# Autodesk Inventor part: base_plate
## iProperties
Created: 2008-04
Part Number: base_plate
Document SubType Name: Modeling
Designer: Jayson Martinez
Density: 1 g/cm^3
Width: 24.000 in
PlateThickness: 0.200 in
Height: 12.000 in
MemberThickness: 0.125 in
MemberWidth: 2.000 in
HorizontalLength: 20.000 in
CornerLength: 12.000 in
SideLength: 8.000 in
Author: Jayson Martinez
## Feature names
1. Extrusion1
2. Split1
